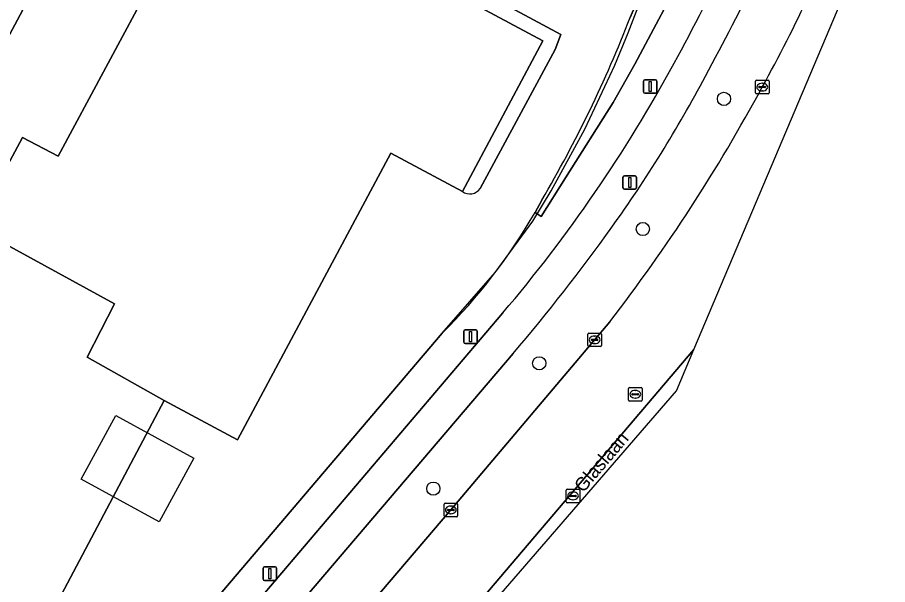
# Model space of a CAD drawing. Extents: x 159489 to 160304, y 383825 to 384531.
# Drawn here: x 160149.6 to 160213.9, y 383889.8 to 383931.7 of the extents above; entities that cross this region are included whole.
import ezdxf

# ---------------------------------------------------------------- set-up
doc = ezdxf.new("R2010")
doc.units = 0
for name, color, linetype in [('IMGEO_Berm_groen', 7, 'Continuous'), ('IMGEO_Boom', 7, 'Continuous'), ('IMGEO_Erf', 7, 'Continuous'), ('IMGEO_Fietspad_gesloten', 7, 'Continuous'), ('IMGEO_Groenvoorziening', 7, 'Continuous'), ('IMGEO_Hek', 7, 'Continuous'), ('IMGEO_Kolk', 7, 'Continuous'), ('IMGEO_Lichtmast', 7, 'Continuous'), ('IMGEO_Openbare_ruimte_label', 7, 'Continuous'), ('IMGEO_Pand', 7, 'Continuous'), ('IMGEO_Pand_vergunning_verleend', 7, 'Continuous'), ('IMGEO_Parkeervlak_open', 7, 'Continuous'), ('IMGEO_Rijbaan_lokaal_gesloten', 7, 'Continuous'), ('IMGEO_Rijbaan_lokaal_open', 7, 'Continuous'), ('IMGEO_Rioolput', 7, 'Continuous'), ('IMGEO_Voetpad_open', 7, 'Continuous')]:
    doc.layers.add(name, color=color, linetype=linetype)

msp = doc.modelspace()

# ---------------------------------------------------------------- linework, layer by layer
at = {"layer": 'IMGEO_Berm_groen'}
for points in [[(160181.634, 383895.343), (160193.375, 383909.247)], [(160186.226, 383906.909), (160150.338, 383864.738)], [(160153.034, 383861.772), (160181.634, 383895.343)]]:
    msp.add_lwpolyline(points, dxfattribs=at)
for centre, radius, start, end in [((160028.77, 384020.501), 195.28, 331.52281, 336.5523), ((160103.573, 383982.339), 115.411, 331.11352, 338.79583), ((160114.949, 383972.573), 96.681, 324.35096, 332.13785), ((160091.78, 383987.48), 128.226, 322.40195, 331.64793), ((160085.669, 383993.053), 132.41, 319.41434, 324.53403)]:
    msp.add_arc(centre, radius, start, end, dxfattribs=at)
at = {"layer": 'IMGEO_Boom'}
for centre in [(160201.799, 383925.713), (160195.812, 383916.098), (160188.162, 383906.178), (160180.339, 383896.918)]:
    msp.add_circle(centre, 0.489, dxfattribs=at)
at = {"layer": 'IMGEO_Erf'}
msp.add_lwpolyline([(160160.47, 383903.419), (160154.77, 383906.62), (160156.806, 383910.583), (160146.426, 383916.245), (160132.339, 383890.119), (160140.933, 383885.524), (160143.282, 383884.269), (160148.779, 383881.33), (160151.308, 383886.109)], close=True, dxfattribs=at)
at = {"layer": 'IMGEO_Fietspad_gesloten'}
for points in [[(160185.469, 383909.903), (160149.897, 383868.032)], [(160150.338, 383864.738), (160186.226, 383906.909)]]:
    msp.add_lwpolyline(points, dxfattribs=at)
for centre, radius, start, end in [((160040.368, 384014.413), 179.698, 331.38357, 337.1919), ((160028.77, 384020.501), 195.28, 331.52281, 336.5523), ((160103.805, 383979.45), 107.264, 319.58151, 331.54897), ((160114.949, 383972.573), 96.681, 324.35096, 332.13785), ((160085.669, 383993.053), 132.41, 319.41434, 324.53403)]:
    msp.add_arc(centre, radius, start, end, dxfattribs=at)
at = {"layer": 'IMGEO_Groenvoorziening'}
for points in [[(160201.293, 383940.15), (160199.061, 383941.199), (160196.513, 383936.468), (160196.707, 383936.364), (160195.65, 383933.577), (160194.881, 383931.736)], [(160188.356, 383918.24), (160187.848, 383917.33), (160188.308, 383917.034), (160190.104, 383919.882), (160193.627, 383925.456), (160195.208, 383928.268), (160199.125, 383935.65), (160201.293, 383940.15)]]:
    msp.add_lwpolyline(points, dxfattribs=at)
msp.add_arc((160105.951, 383966.406), 95.449, 329.69345, 338.70119, dxfattribs=at)
at = {"layer": 'IMGEO_Hek'}
msp.add_lwpolyline([(160180.989, 383908.397), (160184.904, 383912.878), (160187.683, 383916.688), (160189.034, 383918.913), (160191.528, 383923.484), (160193.737, 383928.198), (160194.732, 383930.605), (160196.891, 383936.266)], dxfattribs=at)
at = {"layer": 'IMGEO_Kolk'}
for p, q in [((160204.124, 383926.161), (160204.124, 383927.013)), ((160204.199, 383927.087), (160205.051, 383927.087)), ((160205.125, 383927.013), (160205.125, 383926.161)), ((160204.383, 383926.581), (160204.383, 383926.593)), ((160204.821, 383926.544), (160204.423, 383926.544)), ((160204.426, 383926.63), (160204.824, 383926.63)), ((160204.612, 383926.867), (160204.637, 383926.867)), ((160204.867, 383926.593), (160204.867, 383926.581)), ((160205.051, 383926.087), (160204.199, 383926.087)), ((160204.635, 383926.307), (160204.61, 383926.307)), ((160191.746, 383907.486), (160191.746, 383908.338)), ((160191.821, 383908.412), (160192.673, 383908.412)), ((160192.747, 383908.338), (160192.747, 383907.486)), ((160192.005, 383907.906), (160192.005, 383907.918)), ((160192.443, 383907.869), (160192.045, 383907.869)), ((160192.048, 383907.955), (160192.446, 383907.955)), ((160192.234, 383908.192), (160192.259, 383908.192)), ((160192.489, 383907.918), (160192.489, 383907.906)), ((160192.673, 383907.412), (160191.821, 383907.412)), ((160192.257, 383907.632), (160192.232, 383907.632)), ((160190.146, 383895.952), (160190.146, 383896.804)), ((160190.221, 383896.878), (160191.073, 383896.878)), ((160191.147, 383896.804), (160191.147, 383895.952)), ((160190.405, 383896.372), (160190.405, 383896.384)), ((160190.843, 383896.335), (160190.445, 383896.335)), ((160190.448, 383896.421), (160190.846, 383896.421)), ((160190.634, 383896.658), (160190.659, 383896.658)), ((160190.889, 383896.384), (160190.889, 383896.372)), ((160181.133, 383894.917), (160181.133, 383895.769)), ((160181.208, 383895.843), (160182.06, 383895.843)), ((160181.621, 383895.623), (160181.646, 383895.623)), ((160182.134, 383895.769), (160182.134, 383894.917)), ((160191.073, 383895.878), (160190.221, 383895.878)), ((160190.657, 383896.098), (160190.632, 383896.098)), ((160182.06, 383894.843), (160181.208, 383894.843)), ((160181.392, 383895.337), (160181.392, 383895.349)), ((160181.83, 383895.3), (160181.432, 383895.3)), ((160181.435, 383895.386), (160181.833, 383895.386)), ((160181.644, 383895.063), (160181.619, 383895.063)), ((160181.876, 383895.349), (160181.876, 383895.337))]:
    msp.add_line(p, q, dxfattribs=at)
for points in [[(160204.124, 383926.161), (160204.124, 383927.013)], [(160204.199, 383927.087), (160205.051, 383927.087)], [(160205.125, 383927.013), (160205.125, 383926.161)], [(160205.051, 383926.087), (160204.199, 383926.087)], [(160191.746, 383907.486), (160191.746, 383908.338)], [(160191.821, 383908.412), (160192.673, 383908.412)], [(160192.747, 383908.338), (160192.747, 383907.486)], [(160192.673, 383907.412), (160191.821, 383907.412)], [(160190.146, 383895.952), (160190.146, 383896.804)], [(160190.221, 383896.878), (160191.073, 383896.878)], [(160191.147, 383896.804), (160191.147, 383895.952)], [(160181.133, 383894.917), (160181.133, 383895.769)], [(160181.208, 383895.843), (160182.06, 383895.843)], [(160182.134, 383895.769), (160182.134, 383894.917)], [(160191.073, 383895.878), (160190.221, 383895.878)], [(160182.06, 383894.843), (160181.208, 383894.843)]]:
    msp.add_lwpolyline(points, dxfattribs=at)
for centre, radius, start, end in [((160204.201, 383927.011), 0.0765, 91.55205, 178.44795), ((160204.201, 383927.011), 0.0765, 91.55205, 178.44795), ((160205.049, 383927.011), 0.0765, 1.55205, 88.44795), ((160205.049, 383927.011), 0.0765, 1.55205, 88.44795), ((160204.423, 383926.59), 0.0403, 85.87752, 175.75265), ((160204.42, 383926.58), 0.0366, 178.93798, 274.71019), ((160204.824, 383926.587), 0.043, 264.86636, 352.45326), ((160204.828, 383926.592), 0.0386, 1.73085, 96.63898), ((160204.201, 383926.163), 0.0765, 181.55205, 268.44795), ((160204.201, 383926.163), 0.0765, 181.55205, 268.44795), ((160205.049, 383926.163), 0.0765, 271.55205, 358.44795), ((160205.049, 383926.163), 0.0765, 271.55205, 358.44795), ((160191.823, 383908.336), 0.0765, 91.55205, 178.44795), ((160191.823, 383908.336), 0.0765, 91.55205, 178.44795), ((160192.671, 383908.336), 0.0765, 1.55205, 88.44795), ((160192.671, 383908.336), 0.0765, 1.55205, 88.44795), ((160192.045, 383907.915), 0.0403, 85.87752, 175.75265), ((160192.042, 383907.905), 0.0366, 178.93798, 274.71019), ((160192.446, 383907.912), 0.043, 264.86636, 352.45326), ((160192.45, 383907.917), 0.0386, 1.73085, 96.63898), ((160191.823, 383907.488), 0.0765, 181.55205, 268.44795), ((160191.823, 383907.488), 0.0765, 181.55205, 268.44795), ((160192.671, 383907.488), 0.0765, 271.55205, 358.44795), ((160192.671, 383907.488), 0.0765, 271.55205, 358.44795), ((160190.223, 383896.802), 0.0765, 91.55205, 178.44795), ((160190.223, 383896.802), 0.0765, 91.55205, 178.44795), ((160191.071, 383896.802), 0.0765, 1.55205, 88.44795), ((160191.071, 383896.802), 0.0765, 1.55205, 88.44795), ((160190.445, 383896.381), 0.0403, 85.87752, 175.75265), ((160190.442, 383896.371), 0.0366, 178.93798, 274.71019), ((160190.846, 383896.378), 0.043, 264.86636, 352.45326), ((160190.85, 383896.383), 0.0386, 1.73085, 96.63898), ((160181.21, 383895.767), 0.0765, 91.55205, 178.44795), ((160181.21, 383895.767), 0.0765, 91.55205, 178.44795), ((160182.058, 383895.767), 0.0765, 1.55205, 88.44795), ((160182.058, 383895.767), 0.0765, 1.55205, 88.44795), ((160190.223, 383895.954), 0.0765, 181.55205, 268.44795), ((160190.223, 383895.954), 0.0765, 181.55205, 268.44795), ((160191.071, 383895.954), 0.0765, 271.55205, 358.44795), ((160191.071, 383895.954), 0.0765, 271.55205, 358.44795), ((160181.21, 383894.919), 0.0765, 181.55205, 268.44795), ((160181.21, 383894.919), 0.0765, 181.55205, 268.44795), ((160181.432, 383895.346), 0.0403, 85.87752, 175.75265), ((160181.429, 383895.336), 0.0366, 178.93798, 274.71019), ((160181.833, 383895.343), 0.043, 264.86636, 352.45326), ((160181.837, 383895.348), 0.0386, 1.73085, 96.63898), ((160182.058, 383894.919), 0.0765, 271.55205, 358.44795), ((160182.058, 383894.919), 0.0765, 271.55205, 358.44795)]:
    msp.add_arc(centre, radius, start, end, dxfattribs=at)
for centre, major_axis, ratio, start_param, end_param in [((160204.611, 383926.587), (-0.387, 0.002), 0.722429, 4.712389, 7.853982), ((160204.636, 383926.587), (-0.39, 0.002), 0.717154, 1.570796, 4.712389), ((160192.233, 383907.912), (-0.387, 0.002), 0.722429, 4.712389, 7.853982), ((160192.258, 383907.912), (-0.39, 0.002), 0.717154, 1.570796, 4.712389), ((160190.633, 383896.378), (-0.387, 0.002), 0.722429, 4.712389, 7.853982), ((160190.658, 383896.378), (-0.39, 0.002), 0.717154, 1.570796, 4.712389), ((160181.62, 383895.343), (-0.387, 0.002), 0.722429, 4.712389, 7.853982), ((160181.645, 383895.343), (-0.39, 0.002), 0.717154, 1.570796, 4.712389)]:
    msp.add_ellipse(centre, major_axis=major_axis, ratio=ratio, start_param=start_param, end_param=end_param, dxfattribs=at)
at = {"layer": 'IMGEO_Lichtmast'}
for p, q in [((160195.855, 383926.233), (160195.855, 383927.033)), ((160195.855, 383927.033), (160195.855, 383926.233)), ((160195.955, 383927.133), (160196.745, 383927.133)), ((160196.745, 383927.133), (160195.955, 383927.133)), ((160196.845, 383927.033), (160196.845, 383926.233)), ((160196.845, 383926.233), (160196.845, 383927.033)), ((160196.745, 383926.133), (160195.955, 383926.133)), ((160195.955, 383926.133), (160196.745, 383926.133)), ((160194.342, 383919.132), (160194.342, 383919.932)), ((160194.342, 383919.932), (160194.342, 383919.132)), ((160194.442, 383920.032), (160195.232, 383920.032)), ((160195.232, 383920.032), (160194.442, 383920.032)), ((160195.332, 383919.932), (160195.332, 383919.132)), ((160195.332, 383919.132), (160195.332, 383919.932)), ((160195.232, 383919.032), (160194.442, 383919.032)), ((160194.442, 383919.032), (160195.232, 383919.032)), ((160182.584, 383907.744), (160182.584, 383908.544)), ((160182.584, 383908.544), (160182.584, 383907.744)), ((160182.684, 383908.644), (160183.474, 383908.644)), ((160183.474, 383908.644), (160182.684, 383908.644)), ((160183.574, 383908.544), (160183.574, 383907.744)), ((160183.574, 383907.744), (160183.574, 383908.544)), ((160183.474, 383907.644), (160182.684, 383907.644)), ((160182.684, 383907.644), (160183.474, 383907.644)), ((160167.774, 383890.235), (160167.774, 383891.035)), ((160167.774, 383891.035), (160167.774, 383890.235)), ((160167.874, 383891.135), (160168.664, 383891.135)), ((160168.664, 383891.135), (160167.874, 383891.135)), ((160168.764, 383891.035), (160168.764, 383890.235)), ((160168.764, 383890.235), (160168.764, 383891.035)), ((160168.664, 383890.135), (160167.874, 383890.135)), ((160167.874, 383890.135), (160168.664, 383890.135))]:
    msp.add_line(p, q, dxfattribs=at)
for points in [[(160196.275, 383927.008), (160196.425, 383927.008), (160196.425, 383926.258), (160196.275, 383926.258), (160196.275, 383927.008)], [(160194.762, 383919.907), (160194.912, 383919.907), (160194.912, 383919.157), (160194.762, 383919.157), (160194.762, 383919.907)], [(160183.004, 383908.519), (160183.154, 383908.519), (160183.154, 383907.769), (160183.004, 383907.769), (160183.004, 383908.519)], [(160168.194, 383891.01), (160168.344, 383891.01), (160168.344, 383890.26), (160168.194, 383890.26), (160168.194, 383891.01)]]:
    msp.add_lwpolyline(points, dxfattribs=at)
for centre, start, end in [((160195.955, 383927.033), 90, 180), ((160195.955, 383927.033), 90, 180), ((160196.745, 383927.033), 0, 90), ((160196.745, 383927.033), 360, 90), ((160195.955, 383926.233), 180, 270), ((160195.955, 383926.233), 180, 270), ((160196.745, 383926.233), 270, 0), ((160196.745, 383926.233), 270, 0), ((160194.442, 383919.932), 90, 180), ((160194.442, 383919.932), 90, 180), ((160195.232, 383919.932), 0, 90), ((160195.232, 383919.932), 360, 90), ((160194.442, 383919.132), 180, 270), ((160194.442, 383919.132), 180, 270), ((160195.232, 383919.132), 270, 0), ((160195.232, 383919.132), 270, 0), ((160182.684, 383908.544), 90, 180), ((160182.684, 383908.544), 90, 180), ((160183.474, 383908.544), 0, 90), ((160183.474, 383908.544), 360, 90), ((160182.684, 383907.744), 180, 270), ((160182.684, 383907.744), 180, 270), ((160183.474, 383907.744), 270, 0), ((160183.474, 383907.744), 270, 0), ((160167.874, 383891.035), 90, 180), ((160167.874, 383891.035), 90, 180), ((160168.664, 383891.035), 0, 90), ((160168.664, 383891.035), 360, 90), ((160167.874, 383890.235), 180, 270), ((160167.874, 383890.235), 180, 270), ((160168.664, 383890.235), 270, 0), ((160168.664, 383890.235), 270, 0)]:
    msp.add_arc(centre, 0.1, start, end, dxfattribs=at)
at = {"layer": 'IMGEO_Pand'}
msp.add_lwpolyline([(160177.2, 383921.7), (160182.489, 383918.88), (160188.429, 383930), (160161.44, 383944.46), (160161.14, 383943.909), (160161.239, 383943.859), (160157.04, 383936.02), (160159.67, 383934.609), (160152.64, 383921.489), (160150, 383922.872), (160146.426, 383916.245), (160156.806, 383910.583), (160154.77, 383906.62), (160160.47, 383903.419), (160165.88, 383900.52)], close=True, dxfattribs=at)
at = {"layer": 'IMGEO_Pand_vergunning_verleend'}
msp.add_lwpolyline([(160154.33, 383897.617), (160156.888, 383902.315), (160162.661, 383899.171), (160160.103, 383894.473)], close=True, dxfattribs=at)
at = {"layer": 'IMGEO_Parkeervlak_open'}
msp.add_lwpolyline([(160147.613, 383845.552), (160198.29, 383904.149), (160199.575, 383907.191), (160184.33, 383889.277), (160146.634, 383844.98)], dxfattribs=at)
at = {"layer": 'IMGEO_Rijbaan_lokaal_gesloten'}
for points in [[(160143.008, 383840.818), (160146.634, 383844.98), (160184.33, 383889.277), (160199.575, 383907.191), (160214.457, 383942.419), (160222.454, 383961.352), (160234.176, 383975.482)], [(160193.375, 383909.247), (160181.634, 383895.343), (160153.034, 383861.772)]]:
    msp.add_lwpolyline(points, dxfattribs=at)
for centre, radius, start, end in [((160103.573, 383982.339), 115.411, 331.11352, 338.79583), ((160091.78, 383987.48), 128.226, 322.40195, 331.64793)]:
    msp.add_arc(centre, radius, start, end, dxfattribs=at)
at = {"layer": 'IMGEO_Rijbaan_lokaal_open'}
for points in [[(160194.881, 383931.736), (160195.65, 383933.577), (160196.707, 383936.364), (160196.513, 383936.468), (160178.832, 383945.948), (160161.109, 383955.416), (160157.936, 383957.174), (160151.399, 383960.582), (160139.607, 383966.552)], [(160148.351, 383955.557), (160151.23, 383950.76), (160151.522, 383950.04), (160151.63, 383949.27), (160151.547, 383948.498), (160151.279, 383947.77), (160136.85, 383920.539), (160142.149, 383917.59), (160153.27, 383938.4), (160158.155, 383947.467), (160189.759, 383930.483), (160189.334, 383929.353), (160183.802, 383919.096)], [(160182.489, 383918.88), (160177.2, 383921.7), (160165.88, 383900.52), (160160.47, 383903.419), (160151.308, 383886.109), (160153.62, 383884.978)], [(160187.848, 383917.33), (160188.356, 383918.24)], [(160121.308, 383892.592), (160112.033, 383897.544), (160111.354, 383896.24), (160107.339, 383888.684), (160116.585, 383883.73), (160121.339, 383881.182), (160122.173, 383880.736), (160122.267, 383880.685), (160139.326, 383871.551), (160146.029, 383867.963), (160146.393, 383867.768), (160146.756, 383868.165), (160180.989, 383908.397)]]:
    msp.add_lwpolyline(points, dxfattribs=at)
for centre, radius, start, end in [((160105.951, 383966.406), 95.449, 329.69345, 338.70119), ((160183.043, 383919.611), 0.917, 232.84747, 325.83649), ((160151.242, 383938.337), 42.205, 314.81432, 330.14962)]:
    msp.add_arc(centre, radius, start, end, dxfattribs=at)
at = {"layer": 'IMGEO_Rioolput'}
for p, q in [((160194.748, 383903.462), (160194.748, 383904.314)), ((160194.823, 383904.388), (160195.675, 383904.388)), ((160195.007, 383903.882), (160195.007, 383903.894)), ((160195.445, 383903.845), (160195.047, 383903.845)), ((160195.05, 383903.931), (160195.448, 383903.931)), ((160195.236, 383904.168), (160195.261, 383904.168)), ((160195.491, 383903.894), (160195.491, 383903.882)), ((160195.749, 383904.314), (160195.749, 383903.462)), ((160195.675, 383903.388), (160194.823, 383903.388)), ((160195.259, 383903.608), (160195.234, 383903.608))]:
    msp.add_line(p, q, dxfattribs=at)
for points in [[(160194.748, 383903.462), (160194.748, 383904.314)], [(160194.823, 383904.388), (160195.675, 383904.388)], [(160195.749, 383904.314), (160195.749, 383903.462)], [(160195.675, 383903.388), (160194.823, 383903.388)]]:
    msp.add_lwpolyline(points, dxfattribs=at)
for centre, radius, start, end in [((160194.825, 383904.312), 0.0765, 91.55205, 178.44795), ((160194.825, 383904.312), 0.0765, 91.55205, 178.44795), ((160195.047, 383903.891), 0.0403, 85.87752, 175.75265), ((160195.044, 383903.881), 0.0366, 178.93798, 274.71019), ((160195.448, 383903.888), 0.043, 264.86636, 352.45326), ((160195.452, 383903.893), 0.0386, 1.73085, 96.63898), ((160195.673, 383904.312), 0.0765, 1.55205, 88.44795), ((160195.673, 383904.312), 0.0765, 1.55205, 88.44795), ((160194.825, 383903.464), 0.0765, 181.55205, 268.44795), ((160194.825, 383903.464), 0.0765, 181.55205, 268.44795), ((160195.673, 383903.464), 0.0765, 271.55205, 358.44795), ((160195.673, 383903.464), 0.0765, 271.55205, 358.44795)]:
    msp.add_arc(centre, radius, start, end, dxfattribs=at)
for centre, major_axis, ratio, start_param, end_param in [((160195.235, 383903.888), (-0.387, 0.002), 0.722429, 4.712389, 7.853982), ((160195.26, 383903.888), (-0.39, 0.002), 0.717154, 1.570796, 4.712389)]:
    msp.add_ellipse(centre, major_axis=major_axis, ratio=ratio, start_param=start_param, end_param=end_param, dxfattribs=at)
at = {"layer": 'IMGEO_Voetpad_open'}
for points in [[(160224.175, 383977.046), (160222.175, 383978.311), (160218.883, 383973.89), (160216.197, 383970.382), (160213.201, 383966.234), (160211.861, 383964.14), (160210.086, 383961.009), (160208.315, 383957.395), (160206.839, 383953.974), (160204.164, 383946.923), (160201.293, 383940.15), (160199.125, 383935.65), (160195.208, 383928.268), (160193.627, 383925.456), (160190.104, 383919.882), (160188.308, 383917.034), (160187.848, 383917.33)], [(160183.802, 383919.096), (160189.334, 383929.353), (160189.759, 383930.483), (160158.155, 383947.467), (160153.27, 383938.4), (160142.149, 383917.59), (160140.529, 383914.58), (160127.736, 383890.678)], [(160132.339, 383890.119), (160146.426, 383916.245), (160150, 383922.872), (160152.64, 383921.489), (160159.67, 383934.609), (160157.04, 383936.02), (160161.239, 383943.859), (160161.14, 383943.909), (160161.44, 383944.46), (160188.429, 383930), (160182.489, 383918.88)], [(160149.897, 383868.032), (160185.469, 383909.903)], [(160180.989, 383908.397), (160146.756, 383868.165), (160146.393, 383867.768), (160145.939, 383867.271)]]:
    msp.add_lwpolyline(points, dxfattribs=at)
for centre, radius, start, end in [((160040.368, 384014.413), 179.698, 331.38357, 337.1919), ((160103.805, 383979.45), 107.264, 319.58151, 331.54897), ((160183.043, 383919.611), 0.917, 232.84747, 325.83649), ((160151.242, 383938.337), 42.205, 314.81432, 330.14962)]:
    msp.add_arc(centre, radius, start, end, dxfattribs=at)

# ---------------------------------------------------------------- texts
at = {"layer": 'IMGEO_Openbare_ruimte_label'}
msp.add_text('Glaslaan', height=1, rotation=49.54162, dxfattribs=at).set_placement((160191.407, 383896.563))

doc.saveas('drawing.dxf')
